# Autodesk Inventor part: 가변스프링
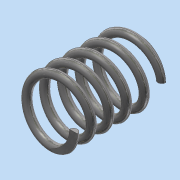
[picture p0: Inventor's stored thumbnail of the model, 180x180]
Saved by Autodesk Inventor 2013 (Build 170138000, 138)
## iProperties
Created: 2019-10
Part Number: 가변스프링
Material: 스테인리스강
Document SubType Name: Modeling
Designer: dgall
Density: 8.08 g/cm^3
Mass: 147.867 g
Surface Area: 124.156 cm^2
Volume: 18.3004 cm^3
Author: dgall
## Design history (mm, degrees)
sketch "스케치1"
  geometry: L1 (0, 0)-(21, 0); L2 (0, 0)-(0, 67.25); L3 (0, 67.25)-(21, 67.25); C1 r 3 at (21, 0)
  constraints: 6 end point, 2 horizontal, 1 centre point, 1 coincident, 1 perpendicular, 1 vertical alignment
  dimensions: "d0" = 42 diameter of L3.end L2; "d2" = 67.25 distance of L1.start L2.end (derived); "d3" = 6 diameter of C1
feature "코일1" sketch "스케치1" pitch "d4" = 10; turns "d6" = 5; dims "d5" = 67.25 (= d2), "d7" = 0, angle "d8" = 90 deg, angle "d9" = 90 deg, "d10" = 0, "d11" = 0
feature "분할1"
node "작업 평면1"
feature "분할2"
node "솔리드1"
other parameters: "d12" = 0
